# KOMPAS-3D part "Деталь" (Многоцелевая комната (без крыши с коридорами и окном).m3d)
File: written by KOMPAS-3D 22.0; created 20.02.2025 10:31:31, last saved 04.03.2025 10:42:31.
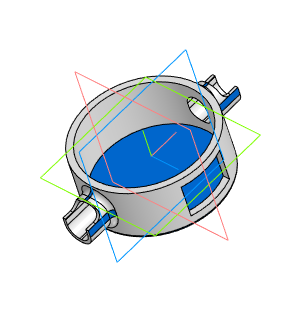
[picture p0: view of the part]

Document properties: Автор: Пользователь Windows; Полное имя файла: C:\Users\Student\Documents\Картошечка\База Сабнатика\Многоцелевая комната\Многоцелевая комната (без крыши с коридорами и окном).m3d

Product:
- Part/product: Деталь
    Масса: 0.112097

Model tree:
1. Эскиз:3
2. Элемент вращения:1
     Угол 1 = 360
3. Скругление:1  (with: Элемент вращения:1)
     Радиус = 1
4. Эскиз:4  (with: Элемент вращения:1)
5. Элемент выдавливания:1
     Расстояние 2 = 6.1
6. Эскиз:5  (with: Элемент выдавливания:1)
7. Элемент выдавливания:2
     Расстояние 2 = 19
8. Смещенная плоскость:1
     Расстояние = 25
9. Эскиз:6
10. Элемент выдавливания:3
     Расстояние 1 = 10; Расстояние 2 = 4
11. Элемент выдавливания:4  (with: Элемент выдавливания:2)
     Расстояние 1 = 22
12. Эскиз:7
13. Элемент выдавливания:5
     Расстояние 2 = 10
14. Скругление:2  (with: Элемент выдавливания:3)
     Радиус = 2
15. Смещенная плоскость:2
     Расстояние = 7
16. Эскиз:8  (with: Элемент выдавливания:3)
17. Элемент выдавливания:6
     Расстояние 2 = 5.5
18. Скругление:3  (with: Элемент выдавливания:6)
     Радиус = 3
19. Зеркальный массив:1
20. Экземпляр ( 1 )
21. Экземпляр ( 2 )  (with: Элемент выдавливания:6, Скругление:3, Элемент выдавливания:3, Скругление:2)
22. Элемент выдавливания:7  (with: Элемент выдавливания:2)
     Расстояние 1 = 21
23. Элемент выдавливания:8
24. Эскиз:9
25. Элемент выдавливания:9
     Расстояние 2 = 30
